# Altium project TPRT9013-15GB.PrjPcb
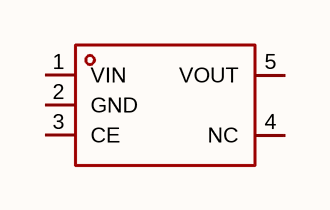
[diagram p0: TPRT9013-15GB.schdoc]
1 sheet, 1 parts. Net scope: global (net labels, ports and power ports of the same name join across sheets).

## Sheet TPRT9013-15GB.schdoc
size 127 x 101 mm

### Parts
U?  tprt9013-15gb  [SOT-23-5_L2.9-W1.6-P0.95-LS2.8-BL]  (value not drawn)

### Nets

Not connected (* = marked no-connect by the designer): U? 1(VIN) 2(GND) 3(CE) 4(NC) 5(VOUT)

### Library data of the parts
U? = tprt9013-15gb: 输出极性:正极;工作电压:7V;输出电压:1.5V;输出电流:500mA;电源纹波抑制比(PSRR):70dB@(1kHz);输出类型:固定;; Manufacturer: TECH PUBLIC(台舟); AddInBom: yes; ModelId: 018c57e721114987ae90467fe9f1d259; ModelTransform: 114.96,110.236,0,0,0,0,0,0,0; Output Configuration: 正极; Voltage - Supply: 7V; Output Voltage: 1.5V; Output Current: 500mA; Voltage Dropout: 100mV@(100mA)；300mV@(200mA); standby current: 60uA; Noise: 50uVrms; Output Type: 固定; Number of Outputs: 1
